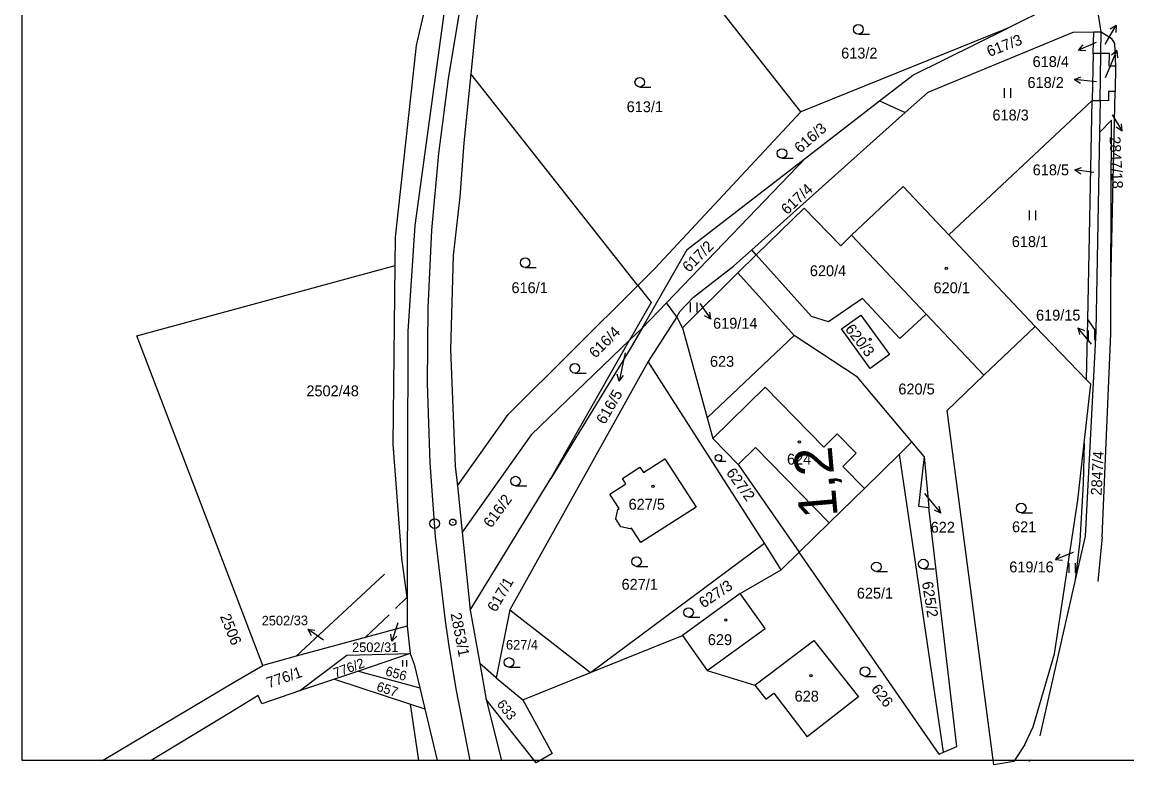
# Model space of a CAD drawing. Extents: x -558358 to -557517, y -1073785 to -1073189.
# Drawn here: x -558357.5 to -558184.5, y -1073784.8 to -1073668.4 of the extents above; entities that cross this region are included whole.
import ezdxf

# ---------------------------------------------------------------- set-up
doc = ezdxf.new("R2010")
doc.units = 0
for name, color, linetype in [('Hranice parcel', 7, 'Continuous'), ('Kolej', 7, 'Continuous'), ('Návěst místo trati', 7, 'Continuous'), ('Parcelní čísla', 7, 'Continuous'), ('Pop  PČ popisy', 7, 'Continuous'), ('Svazek obcí údolí Desné', 7, 'Continuous'), ('Vnitřní kresba', 7, 'Continuous'), ('Vrstva 1', 7, 'Continuous'), ('Značky budov', 7, 'Continuous'), ('Značky kultur', 7, 'Continuous')]:
    doc.layers.add(name, color=color, linetype=linetype)

msp = doc.modelspace()

# ---------------------------------------------------------------- linework, layer by layer
at = {"layer": 'Hranice parcel'}
for p, q in [((-558235.56, -1073682.51), (-558250.61, -1073663.38)), ((-558188.53, -1073669.97), (-558189.35, -1073664.58)), ((-558196.23, -1073665.95), (-558203.14, -1073669.36)), ((-558203.14, -1073669.36), (-558235.56, -1073682.51)), ((-558189.77, -1073673.37), (-558189.69, -1073669.98)), ((-558189.69, -1073669.98), (-558188.53, -1073669.97)), ((-558188.59, -1073673.36), (-558188.53, -1073669.97)), ((-558188.53, -1073669.97), (-558186.98, -1073670.93)), ((-558189.77, -1073673.37), (-558189.93, -1073680.69)), ((-558188.59, -1073673.36), (-558189.77, -1073673.37)), ((-558188.72, -1073680.72), (-558188.59, -1073673.36)), ((-558187.23, -1073673.34), (-558188.59, -1073673.36)), ((-558186.31, -1073675.34), (-558186.36, -1073679.31)), ((-558261.12, -1073709.7), (-558287.25, -1073676.53)), ((-558234.84, -1073689.73), (-558223.26, -1073680.77)), ((-558223.26, -1073680.77), (-558219.23, -1073682.6)), ((-558189.93, -1073680.69), (-558212.4, -1073701.75)), ((-558190.64, -1073715.05), (-558189.93, -1073680.69)), ((-558189.93, -1073680.69), (-558188.72, -1073680.72)), ((-558188.72, -1073680.72), (-558188.81, -1073685.75)), ((-558187.4, -1073680.75), (-558188.72, -1073680.72)), ((-558187.01, -1073709.55), (-558186.36, -1073679.31)), ((-558243.24, -1073704.13), (-558219.23, -1073682.6)), ((-558186.92, -1073683.79), (-558188.81, -1073685.75)), ((-558187.01, -1073709.55), (-558186.92, -1073683.79)), ((-558188.81, -1073685.75), (-558189.35, -1073716.89)), ((-558256.63, -1073712.41), (-558234.84, -1073689.73)), ((-558227.63, -1073701.8), (-558215.96, -1073714.16)), ((-558212.4, -1073701.75), (-558198.87, -1073716.11)), ((-558245.46, -1073707.69), (-558242.57, -1073704.88)), ((-558242.57, -1073704.88), (-558243.24, -1073704.13)), ((-558233.91, -1073714.56), (-558242.57, -1073704.88)), ((-558339.57, -1073717.56), (-558299.09, -1073706.57)), ((-558245.46, -1073707.69), (-558254.11, -1073716.3)), ((-558236.6, -1073717.53), (-558245.46, -1073707.69)), ((-558256.63, -1073712.41), (-558260.45, -1073716.38)), ((-558255.01, -1073714.6), (-558256.63, -1073712.41)), ((-558255.01, -1073714.6), (-558259.48, -1073721.62)), ((-558254.11, -1073716.3), (-558255.01, -1073714.6)), ((-558206.91, -1073723.76), (-558215.96, -1073714.16)), ((-558190.86, -1073724.46), (-558190.64, -1073715.05)), ((-558190.64, -1073715.05), (-558189.35, -1073716.89)), ((-558262.39, -1073718.25), (-558260.45, -1073716.38)), ((-558254.11, -1073716.3), (-558250.26, -1073730.4)), ((-558198.87, -1073716.11), (-558206.91, -1073723.76)), ((-558190.86, -1073724.46), (-558198.87, -1073716.11)), ((-558319.85, -1073769.2), (-558339.57, -1073717.56)), ((-558274.72, -1073739.9), (-558262.39, -1073718.25)), ((-558250.26, -1073730.4), (-558236.6, -1073717.53)), ((-558226.69, -1073724.03), (-558236.6, -1073717.53)), ((-558259.48, -1073721.62), (-558281.15, -1073760.49)), ((-558241.29, -1073750.06), (-558259.48, -1073721.62)), ((-558218.17, -1073734.19), (-558226.69, -1073724.03)), ((-558250.26, -1073730.4), (-558249.36, -1073733.68)), ((-558220.12, -1073736.1), (-558218.17, -1073734.19)), ((-558216.24, -1073736.49), (-558218.17, -1073734.19)), ((-558191.18, -1073734.38), (-558191.35, -1073740.76)), ((-558213.21, -1073782.82), (-558220.12, -1073736.1)), ((-558216.24, -1073736.49), (-558215.54, -1073744.47)), ((-558287.34, -1073760.54), (-558274.72, -1073739.9)), ((-558191.35, -1073740.76), (-558191.89, -1073749.68)), ((-558191.89, -1073749.68), (-558192.59, -1073755.8)), ((-558188.37, -1073749.08), (-558189.08, -1073756.06)), ((-558268.5, -1073770.34), (-558241.29, -1073750.06)), ((-558238.63, -1073754.22), (-558241.29, -1073750.06)), ((-558235.84, -1073751.49), (-558238.63, -1073754.22)), ((-558213.89, -1073783.12), (-558235.84, -1073751.49)), ((-558300.8, -1073754.92), (-558314.63, -1073767.78)), ((-558245.1, -1073757.92), (-558238.63, -1073754.22)), ((-558192.59, -1073755.8), (-558198.14, -1073780.25)), ((-558245.1, -1073757.92), (-558254.1, -1073764.51)), ((-558300.06, -1073761.28), (-558303.78, -1073764.84)), ((-558281.15, -1073760.49), (-558283.28, -1073771.17)), ((-558281.15, -1073760.49), (-558268.5, -1073770.34)), ((-558297.22, -1073763.06), (-558303.78, -1073764.84)), ((-558303.78, -1073764.84), (-558314.63, -1073767.78)), ((-558268.5, -1073770.34), (-558254.1, -1073764.51)), ((-558254.1, -1073764.51), (-558250.25, -1073769.98)), ((-558314.63, -1073767.78), (-558319.85, -1073769.2)), ((-558296.74, -1073767.33), (-558304.84, -1073770.08)), ((-558283.28, -1073771.17), (-558285.85, -1073768.92)), ((-558324.15, -1073771.75), (-558319.85, -1073769.2)), ((-558304.84, -1073770.08), (-558308.63, -1073771.36)), ((-558304.84, -1073770.08), (-558295.26, -1073772.72)), ((-558279.1, -1073774.62), (-558268.5, -1073770.34)), ((-558250.25, -1073769.98), (-558242.76, -1073772.31)), ((-558344.95, -1073784.09), (-558324.15, -1073771.75)), ((-558308.63, -1073771.36), (-558314.07, -1073773.21)), ((-558308.63, -1073771.36), (-558296.72, -1073775.29)), ((-558283.28, -1073771.17), (-558279.1, -1073774.62)), ((-558314.07, -1073773.21), (-558319.99, -1073775.22)), ((-558326.38, -1073777.46), (-558337.3, -1073784.09)), ((-558323.98, -1073776), (-558326.38, -1073777.46)), ((-558213.89, -1073783.12), (-558213.21, -1073782.82))]:
    msp.add_line(p, q, dxfattribs=at)
for points in [[(-558223.26, -1073680.77), (-558218.03, -1073676.72), (-558203.14, -1073669.36)], [(-558219.23, -1073682.6), (-558215.65, -1073679.39), (-558192.95, -1073670.01), (-558189.69, -1073669.98)], [(-558186.98, -1073670.93), (-558186.43, -1073671.79), (-558186.31, -1073675.34)], [(-558186.31, -1073675.34), (-558187.29, -1073675.33), (-558187.23, -1073673.34)], [(-558186.36, -1073679.31), (-558187.4, -1073679.28), (-558187.4, -1073680.75)], [(-558235.56, -1073682.51), (-558258.46, -1073707.03), (-558261.12, -1073709.7)], [(-558260.45, -1073716.38), (-558253.37, -1073704.07), (-558234.84, -1073689.73)], [(-558227.63, -1073701.8), (-558219.54, -1073694.18), (-558212.4, -1073701.75)], [(-558242.57, -1073704.88), (-558235.04, -1073697.59), (-558229.33, -1073703.46), (-558227.63, -1073701.8)], [(-558255.01, -1073714.6), (-558254.51, -1073713.78), (-558252.39, -1073711.53), (-558246.1, -1073706.69), (-558243.24, -1073704.13)], [(-558289.37, -1073741.07), (-558281.4, -1073729.91), (-558261.12, -1073709.7)], [(-558261.12, -1073709.7), (-558259.03, -1073712.35), (-558262.39, -1073718.25)], [(-558188.37, -1073749.08), (-558187.04, -1073717.25), (-558187.01, -1073709.55)], [(-558215.96, -1073714.16), (-558220.05, -1073717.99), (-558225.94, -1073711.71), (-558231.23, -1073715.41), (-558233.91, -1073714.56)], [(-558224.7, -1073722.72), (-558229.2, -1073716.48), (-558226.19, -1073714.33), (-558221.69, -1073720.48), (-558224.7, -1073722.72)], [(-558260.45, -1073716.38), (-558262.32, -1073719.63), (-558274.72, -1073739.9)], [(-558189.35, -1073716.89), (-558191.03, -1073748.95), (-558192.59, -1073755.8)], [(-558262.39, -1073718.25), (-558277.79, -1073733.11), (-558288.61, -1073748.35)], [(-558200.5, -1073781.61), (-558202.2, -1073784.23), (-558205.35, -1073784.79), (-558212.68, -1073729.29), (-558206.91, -1073723.76)], [(-558191.18, -1073734.38), (-558190.17, -1073725.16), (-558190.86, -1073724.46)], [(-558249.36, -1073733.68), (-558245.38, -1073737.75), (-558235.84, -1073751.49)], [(-558200.5, -1073781.61), (-558199.18, -1073778.85), (-558195.83, -1073767.37), (-558192.17, -1073743.33), (-558191.18, -1073734.38)], [(-558235.84, -1073751.49), (-558231.13, -1073746.88), (-558225.62, -1073741.49), (-558220.12, -1073736.1)], [(-558264.25, -1073744.77), (-558264.05, -1073744.64), (-558265.49, -1073742.37), (-558262.97, -1073740.76), (-558263.51, -1073739.92), (-558260.77, -1073738.16), (-558260.22, -1073739), (-558256.85, -1073736.83), (-558251.99, -1073744.42), (-558260.65, -1073749.95), (-558262.08, -1073747.68), (-558262.29, -1073747.81), (-558263.76, -1073747.5), (-558264.56, -1073746.23), (-558264.25, -1073744.77)], [(-558216.24, -1073736.49), (-558217.14, -1073744.24), (-558215.54, -1073744.47)], [(-558213.21, -1073782.82), (-558211.14, -1073781.9), (-558215.54, -1073744.47)], [(-558250.25, -1073769.98), (-558241.14, -1073763.44), (-558245.1, -1073757.92)], [(-558242.76, -1073772.31), (-558233.55, -1073765.31), (-558226.57, -1073774.11), (-558234.56, -1073780.4)], [(-558314.07, -1073773.21), (-558306.66, -1073767.6), (-558296.74, -1073767.33)], [(-558242.76, -1073772.31), (-558241.08, -1073774.51), (-558239.8, -1073773.53), (-558234.56, -1073780.4)], [(-558319.99, -1073775.22), (-558320.55, -1073773.92), (-558323.98, -1073776)], [(-558279.1, -1073774.62), (-558274.51, -1073783), (-558277.02, -1073784.45), (-558284.85, -1073774.53)]]:
    msp.add_lwpolyline(points, dxfattribs=at)
at = {"layer": 'Kolej'}
msp.add_lwpolyline([(-558287.38, -1073784.09), (-558289.56, -1073772.87), (-558290.66, -1073766.21), (-558291.24, -1073762.21), (-558292.77, -1073749.06), (-558293.62, -1073737.47), (-558294.02, -1073725.05), (-558293.93, -1073713.18), (-558293.34, -1073701.02), (-558292.27, -1073689.01), (-558290.77, -1073677.31), (-558288.8, -1073665.65), (-558286.32, -1073653.74), (-558283.34, -1073641.94), (-558280, -1073630.57), (-558276.23, -1073619.43), (-558271.87, -1073608.04), (-558267.23, -1073597.24), (-558261.98, -1073586.24), (-558256.49, -1073575.8), (-558250.41, -1073565.28), (-558246.06, -1073558.3), (-558241.22, -1073550.9)], dxfattribs=at)
at = {"layer": 'Návěst místo trati'}
msp.add_line((-558290.15, -1073746.78), (-558290.05, -1073746.78), dxfattribs=at)
for centre, radius in [((-558292.92, -1073746.99), 0.75), ((-558290.09, -1073746.78), 0.5)]:
    msp.add_circle(centre, radius, dxfattribs=at)
at = {"layer": 'Pop  PČ popisy'}
for p, q in [((-558187.72, -1073671.53), (-558186.17, -1073668.96)), ((-558186.17, -1073668.96), (-558187.12, -1073669.56)), ((-558186.17, -1073668.96), (-558186.26, -1073670.07)), ((-558189.32, -1073671.65), (-558192.08, -1073672.82)), ((-558192.08, -1073672.82), (-558191.36, -1073671.97)), ((-558187.93, -1073671.89), (-558187.72, -1073671.53)), ((-558192.08, -1073672.82), (-558190.96, -1073672.89)), ((-558187.24, -1073675.66), (-558186.07, -1073672.9)), ((-558186.07, -1073672.9), (-558186.92, -1073673.62)), ((-558186.07, -1073672.9), (-558186, -1073674.02)), ((-558192.74, -1073677.42), (-558191.7, -1073677.02)), ((-558187.86, -1073677.09), (-558187.24, -1073675.66)), ((-558189.76, -1073677.73), (-558192.74, -1073677.42)), ((-558192.74, -1073677.42), (-558191.8, -1073678.02)), ((-558189.29, -1073677.78), (-558189.76, -1073677.73)), ((-558186.84, -1073682.95), (-558185.25, -1073685.5)), ((-558185.25, -1073685.5), (-558186.2, -1073684.91)), ((-558185.25, -1073685.5), (-558185.36, -1073684.38)), ((-558192.66, -1073691.6), (-558191.6, -1073691.23)), ((-558189.68, -1073691.97), (-558192.66, -1073691.6)), ((-558192.66, -1073691.6), (-558191.73, -1073692.22)), ((-558251.41, -1073712.52), (-558249.69, -1073714.98)), ((-558249.69, -1073714.98), (-558250.67, -1073714.45)), ((-558249.69, -1073714.98), (-558249.85, -1073713.87)), ((-558190.25, -1073718.6), (-558192.18, -1073716.3)), ((-558192.18, -1073716.3), (-558191.15, -1073716.75)), ((-558192.18, -1073716.3), (-558191.92, -1073717.39)), ((-558190.03, -1073718.86), (-558190.25, -1073718.6)), ((-558263.11, -1073720.25), (-558263.42, -1073721.72)), ((-558263.42, -1073721.72), (-558264.04, -1073724.66)), ((-558264.04, -1073724.66), (-558264.33, -1073723.57)), ((-558264.04, -1073724.66), (-558263.35, -1073723.78)), ((-558216.21, -1073742.3), (-558215.56, -1073743.06)), ((-558215.56, -1073743.06), (-558213.63, -1073745.36)), ((-558213.63, -1073745.36), (-558213.89, -1073744.27)), ((-558213.63, -1073745.36), (-558214.66, -1073744.91)), ((-558192.9, -1073751.52), (-558195.7, -1073752.59)), ((-558192.88, -1073751.51), (-558192.9, -1073751.52)), ((-558195.7, -1073752.59), (-558194.95, -1073751.77)), ((-558195.7, -1073752.59), (-558194.59, -1073752.7)), ((-558310.33, -1073765.25), (-558312.78, -1073763.52)), ((-558312.78, -1073763.52), (-558311.67, -1073763.69)), ((-558312.78, -1073763.52), (-558312.25, -1073764.51)), ((-558298.67, -1073762.56), (-558299.62, -1073765.4)), ((-558299.62, -1073765.4), (-558299.78, -1073764.29)), ((-558299.62, -1073765.4), (-558298.83, -1073764.61)), ((-558199.56, -1073784.03), (-558199.85, -1073784.27))]:
    msp.add_line(p, q, dxfattribs=at)
at = {"layer": 'Svazek obcí údolí Desné'}
for p, q in [((-558289.37, -1073741.07), (-558288.61, -1073748.35)), ((-558288.61, -1073748.35), (-558287.34, -1073760.54)), ((-558297.21, -1073758.56), (-558298.08, -1073752.4)), ((-558297.21, -1073758.56), (-558297.22, -1073763.06)), ((-558287.34, -1073760.54), (-558285.85, -1073768.92)), ((-558297.22, -1073763.06), (-558296.74, -1073767.33)), ((-558285.85, -1073768.92), (-558284.85, -1073774.53)), ((-558295.26, -1073772.72), (-558294.47, -1073776.03)), ((-558296.72, -1073775.29), (-558294.47, -1073776.03)), ((-558284.85, -1073774.53), (-558282.48, -1073784.09))]:
    msp.add_line(p, q, dxfattribs=at)
for points in [[(-558237.23, -1073540.41), (-558250.35, -1073559.71), (-558264.4, -1073584.99), (-558277.08, -1073613.49), (-558283.33, -1073632.3), (-558290.3, -1073658.29), (-558296.01, -1073700.28), (-558297.13, -1073716.84), (-558297.21, -1073758.56)], [(-558299.09, -1073706.57), (-558299.03, -1073702.13), (-558295.75, -1073672.1), (-558286.79, -1073633.11)], [(-558281.64, -1073647.46), (-558284.84, -1073659.61), (-558286.44, -1073668.26), (-558287.25, -1073676.53)], [(-558287.25, -1073676.53), (-558288.33, -1073687.34), (-558288.98, -1073695.83), (-558290.03, -1073705.01), (-558290.44, -1073719.74), (-558289.69, -1073738.01), (-558289.37, -1073741.07)], [(-558298.08, -1073752.4), (-558299.44, -1073734.57), (-558299.09, -1073706.57)], [(-558296.74, -1073767.33), (-558296.14, -1073769.02), (-558295.26, -1073772.72)], [(-558295.38, -1073784.09), (-558296.72, -1073775.29)], [(-558294.47, -1073776.03), (-558292.55, -1073784.09)]]:
    msp.add_lwpolyline(points, dxfattribs=at)
at = {"layer": 'Vnitřní kresba'}
for p, q in [((-558249.36, -1073733.68), (-558241.14, -1073725.64)), ((-558241.14, -1073725.64), (-558231.97, -1073735)), ((-558231.97, -1073735), (-558229.86, -1073732.94)), ((-558229.86, -1073732.94), (-558226.91, -1073735.96)), ((-558245.38, -1073737.75), (-558242.66, -1073735.09)), ((-558242.66, -1073735.09), (-558231.13, -1073746.88)), ((-558229.02, -1073738.02), (-558226.91, -1073735.96)), ((-558229.02, -1073738.02), (-558225.62, -1073741.49))]:
    msp.add_line(p, q, dxfattribs=at)
at = {"layer": 'Vrstva 1'}
for p, q in [((-558357.53, -1073784.09), (-558357.53, -1073190.09)), ((-558298.14, -1073752.46), (-558298.07, -1073752.46)), ((-558299.04, -1073760.31), (-558297.22, -1073758.49)), ((-557516.53, -1073784.09), (-558357.53, -1073784.09))]:
    msp.add_line(p, q, dxfattribs=at)
at = {"layer": 'Značky budov'}
for centre in [(-558212.8, -1073706.99), (-558224.72, -1073718.13), (-558235.8, -1073734.21), (-558258.73, -1073741.17), (-558247.32, -1073762.08), (-558233.99, -1073770.82)]:
    msp.add_circle(centre, 0.175, dxfattribs=at)
at = {"layer": 'Značky kultur'}
for p, q in [((-558226.57, -1073670.32), (-558224.82, -1073670.32)), ((-558260.8, -1073678.6), (-558259.05, -1073678.6)), ((-558203.68, -1073680.3), (-558203.68, -1073678.8)), ((-558202.68, -1073680.3), (-558202.68, -1073678.8)), ((-558238.53, -1073689.76), (-558236.78, -1073689.76)), ((-558199.75, -1073699.45), (-558199.75, -1073697.95)), ((-558198.75, -1073699.45), (-558198.75, -1073697.95)), ((-558278.75, -1073706.87), (-558277, -1073706.87)), ((-558252.83, -1073713.85), (-558252.83, -1073712.35)), ((-558251.83, -1073713.85), (-558251.83, -1073712.35)), ((-558190.54, -1073718.24), (-558190.54, -1073716.74)), ((-558189.54, -1073718.24), (-558189.54, -1073716.74)), ((-558270.97, -1073723.41), (-558269.22, -1073723.41)), ((-558248.47, -1073737.19), (-558247.3, -1073737.19)), ((-558280.25, -1073741.08), (-558278.5, -1073741.08)), ((-558201.06, -1073745.3), (-558199.31, -1073745.3)), ((-558193.57, -1073754.69), (-558193.57, -1073753.19)), ((-558192.57, -1073754.69), (-558192.57, -1073753.19)), ((-558261.31, -1073753.69), (-558259.56, -1073753.69)), ((-558223.74, -1073754.51), (-558221.99, -1073754.51)), ((-558216.38, -1073754.08), (-558214.63, -1073754.08)), ((-558253.16, -1073761.67), (-558251.41, -1073761.67)), ((-558297.93, -1073769.39), (-558297.93, -1073768.39)), ((-558297.26, -1073769.39), (-558297.26, -1073768.39)), ((-558281.28, -1073769.49), (-558279.53, -1073769.49)), ((-558225.53, -1073770.92), (-558223.78, -1073770.92))]:
    msp.add_line(p, q, dxfattribs=at)
for centre, radius in [((-558226.57, -1073669.57), 0.75), ((-558260.8, -1073677.85), 0.75), ((-558238.53, -1073689.01), 0.75), ((-558278.75, -1073706.12), 0.75), ((-558270.97, -1073722.66), 0.75), ((-558248.48, -1073736.69), 0.502), ((-558280.25, -1073740.33), 0.75), ((-558201.06, -1073744.55), 0.75), ((-558261.3, -1073752.94), 0.75), ((-558223.74, -1073753.76), 0.75), ((-558216.38, -1073753.33), 0.75), ((-558253.16, -1073760.92), 0.75), ((-558281.28, -1073768.74), 0.75), ((-558225.53, -1073770.17), 0.75)]:
    msp.add_circle(centre, radius, dxfattribs=at)

# ---------------------------------------------------------------- texts
at = {"layer": 'Návěst místo trati'}
msp.add_text('1,2', height=6, rotation=95.054, dxfattribs=at).set_placement((-558229.78, -1073745.86))
at = {"layer": 'Parcelní čísla'}
for s, height, rotation, p in [('617/3', 1.7, 21, (-558206.06, -1073673.9)), ('616/3', 1.7, 41, (-558235.68, -1073689.06)), ('2847/18', 1.7, 273, (-558187.23, -1073686.37)), ('617/4', 1.7, 43, (-558237.71, -1073698.7)), ('617/2', 1.7, 45, (-558253.11, -1073707.74)), ('616/4', 1.7, 45, (-558267.74, -1073721.18)), ('620/3', 1.7, 308, (-558228.73, -1073716.55)), ('616/5', 1.7, 60, (-558266.27, -1073731.57)), ('2847/4', 1.7, 87, (-558188.48, -1073742.63)), ('627/2', 1.7, 306, (-558247.35, -1073739.04)), ('616/2', 1.7, 54, (-558284.06, -1073747.79)), ('617/1', 1.7, 60, (-558283.33, -1073760.96)), ('627/3', 1.7, 34, (-558250.81, -1073760.3)), ('625/2', 1.7, 279, (-558216.61, -1073756.19)), ('2506', 1.7, 292, (-558326.57, -1073761.52)), ('2502/33', 1.5, 0.4465, (-558320.01, -1073762.95)), ('776/2', 1.5, 20, (-558308.48, -1073771.15)), ('776/1', 1.7, 18.8548, (-558318.91, -1073772.79)), ('656', 1.5, 344, (-558300.76, -1073770.72)), ('657', 1.5, 342, (-558302.15, -1073773.13)), ('626', 1.7, 308, (-558224.66, -1073772.94)), ('633', 1.5, 308, (-558283.26, -1073775.29))]:
    msp.add_text(s, height=height, rotation=rotation, dxfattribs=at).set_placement(p)
for s, height, p in [('613/2', 1.7, (-558229.26, -1073674.14)), ('618/4', 1.7, (-558199.28, -1073675.47)), ('618/2', 1.7, (-558200.08, -1073678.75)), ('613/1', 1.7, (-558262.85, -1073682.54)), ('618/3', 1.7, (-558205.57, -1073683.84)), ('618/5', 1.7, (-558199.26, -1073692.43)), ('618/1', 1.7, (-558202.54, -1073703.67)), ('620/4', 1.7, (-558234.16, -1073708.23)), ('616/1', 1.7, (-558280.89, -1073710.89)), ('620/1', 1.7, (-558214.79, -1073710.9)), ('619/15', 1.7, (-558198.74, -1073715.19)), ('619/14', 1.7, (-558249.32, -1073716.46)), ('623', 1.7, (-558249.81, -1073722.43)), ('2502/48', 1.7, (-558313.01, -1073727.05)), ('620/5', 1.7, (-558220.3, -1073726.76)), ('624', 1.7, (-558237.74, -1073737.75)), ('627/5', 1.7, (-558262.55, -1073744.81)), ('622', 1.7, (-558215.24, -1073748.41)), ('621', 1.7, (-558202.5, -1073748.34)), ('619/16', 1.7, (-558202.93, -1073754.63)), ('627/1', 1.7, (-558263.65, -1073757.35)), ('625/1', 1.7, (-558226.81, -1073758.74)), ('2502/31', 1.5, (-558305.86, -1073767.11)), ('627/4', 1.5, (-558281.75, -1073766.72)), ('629', 1.7, (-558250.14, -1073766.02)), ('628', 1.7, (-558236.55, -1073774.87))]:
    msp.add_text(s, height=height, dxfattribs=at).set_placement(p)
at = {"layer": 'Vrstva 1'}
msp.add_text('2853/1', height=1.7, rotation=281, dxfattribs=at).set_placement((-558290.44, -1073761.12))

doc.saveas('drawing.dxf')
